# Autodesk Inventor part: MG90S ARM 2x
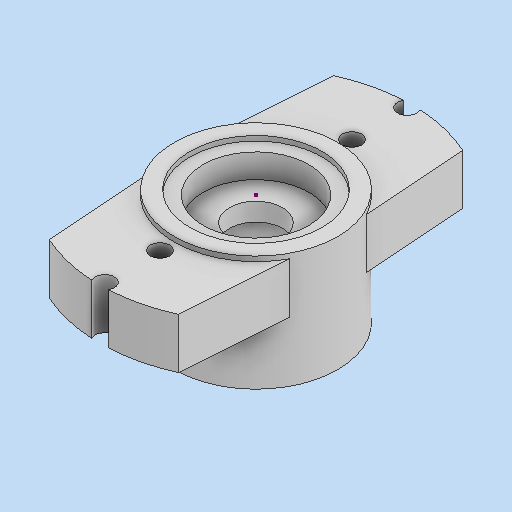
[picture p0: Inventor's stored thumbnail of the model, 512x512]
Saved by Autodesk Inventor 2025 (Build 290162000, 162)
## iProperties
Created: 2026-03
Part Number: MG90S ARM 2x
Material: Generico
Document SubType Name: Modeling
Designer: Ryzen5700u
Density: 1 g/cm^3
Appearance: Default
Author: Ryzen5700u
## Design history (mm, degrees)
node "Geometria corretta1"
  node "Schizzo1-Invisible"
feature "Solido1"
sketch "Schizzo2-Invisible"
node "Schizzo9-Invisible"
node "Schizzo5-Invisible"
sketch "Schizzo3-Invisible"
node "Schizzo6-Invisible"
sketch "Schizzo7-Invisible"
node "Schizzo8"
node "Solido2"
